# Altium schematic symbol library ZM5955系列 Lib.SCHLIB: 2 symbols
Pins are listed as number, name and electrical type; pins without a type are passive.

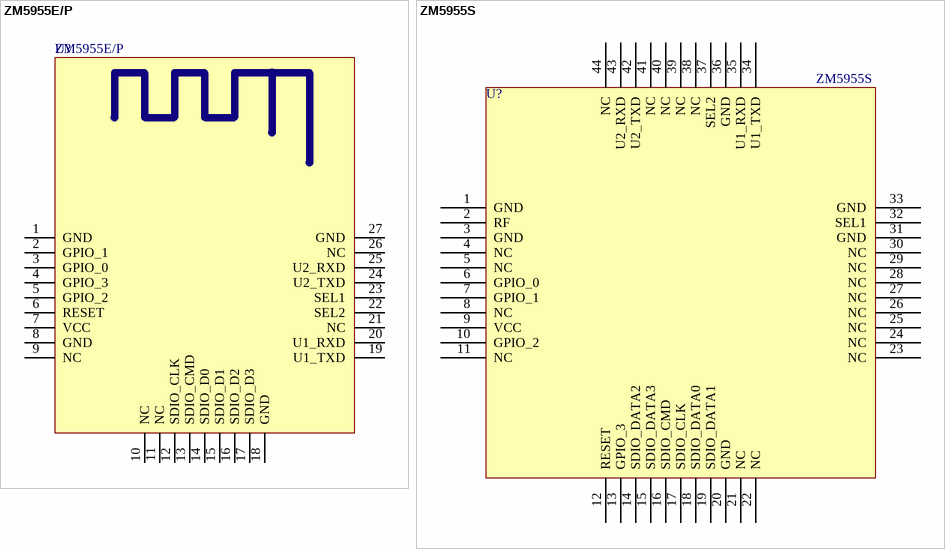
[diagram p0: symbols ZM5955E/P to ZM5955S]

## ZM5955E/P
designator U?
名称: Wi-Fi模块; 厂商: ZHIYUAN; 贴片和直插: SMT; 生产单位: PCS
footprint ZM5955P_REVA
pins: 1 GND, 2 GPIO_1, 3 GPIO_0, 4 GPIO_3, 5 GPIO_2, 6 RESET, 7 VCC, 8 GND, 9 NC, 10 NC, 11 NC, 12 SDIO_CLK, 13 SDIO_CMD, 14 SDIO_D0, 15 SDIO_D1, 16 SDIO_D2, 17 SDIO_D3, 18 GND, 19 U1_TXD, 20 U1_RXD, 21 NC, 22 SEL2, 23 SEL1, 24 U2_TXD, 25 U2_RXD, 26 NC, 27 GND

## ZM5955S
designator U?
名称: Wi-Fi模块; 厂商: ZHIYUAN; 贴片和直插: SMT; 生产单位: PCS
footprint ZM5955S
pins: 1 GND (power), 2 RF, 3 GND (power), 4 NC, 5 NC, 6 GPIO_0, 7 GPIO_1, 8 NC, 9 VCC (power), 10 GPIO_2, 11 NC, 12 RESET, 13 GPIO_3, 14 SDIO_DATA2, 15 SDIO_DATA3, 16 SDIO_CMD, 17 SDIO_CLK, 18 SDIO_DATA0, 19 SDIO_DATA1, 20 GND (power), 21 NC (power), 22 NC (power), 23 NC (power), 24 NC, 25 NC, 26 NC, 27 NC, 28 NC, 29 NC, 30 NC, 31 GND (power), 32 SEL1, 33 GND (power), 34 U1_TXD, 35 U1_RXD, 36 GND (power), 37 SEL2, 38 NC, 39 NC, 40 NC, 41 NC, 42 U2_TXD, 43 U2_RXD, 44 NC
